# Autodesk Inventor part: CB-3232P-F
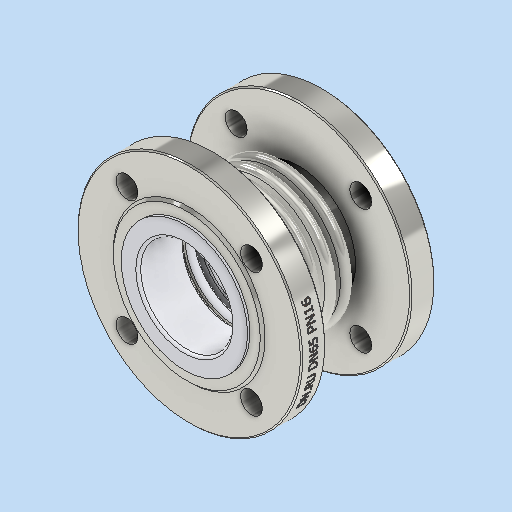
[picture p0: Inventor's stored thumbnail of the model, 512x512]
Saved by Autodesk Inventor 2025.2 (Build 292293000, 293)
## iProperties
Company: DN.RU
Created: 2026-04
Part Number: CB-3232P-F
Material: Типовые
Document SubType Name: Modeling
Designer: DN.RU
Density: 6.22746 g/cm^3
Appearance: По умолчанию
Description: D140-02139
Mass: 6300 g
Surface Area: 2420.54 cm^2
Volume: 1011.65 cm^3
Author: DN.RU
Title: Компенсатор сильфонный осевой DN.ru Ду65 Ру16
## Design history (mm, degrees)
sketch "Эскиз1"
  geometry: L1 (0, 0)-(0, -55); L2 (44, -55)-(44, 0); L3 (44, 0)-(0, 0); L4 (44, 0)-(44, -6.5); L5 (34, -6.5)-(54, -6.5); L6 (34, -10.5)-(54, -10.5); L7 (54, -2.5)-(34, -2.5); L8 (54, -8.5)-(34, -8.5); L9 (34, -4.5)-(54, -4.5); L10 (54, -15.5)-(34, -15.5); L11 (34, -17.5)-(54, -17.5); L12 (34, -19.5)-(54, -19.5); L13 (34, -23.5)-(54, -23.5); L14 (54, -21.5)-(34, -21.5); L15 (0, -55)-(44, -55); L16 (44, -55)-(38, -55); L17 (38, -55)-(38, -21.5); L18 (44, -17.5)-(42, -17.5); L19 (42, -17.5)-(42, -8.5); L20 (44, -4.5)-(42, -4.5); L21 (42, -4.5)-(42, 0); L22 (0, -55)-(0, -35); L23 (0, -35)-(92.5, -35); L24 (92.5, -35)-(92.5, -55); L25 (92.5, -55)-(0, -55); L26 (44, -35)-(44, -45); L27 (44, -45)-(47, -45); L28 (47, -45)-(47, -35); L29 (47, -35)-(44, -35); A1 r 4 centre (34, -6.5) between (34, -2.5) and (34, -10.5); A2 r 4 centre (54, -6.5) between (54, -10.5) and (54, -2.5); A3 r 2 centre (34, -6.5) between (34, -4.5) and (34, -8.5); A4 r 2 centre (54, -6.5) between (54, -8.5) and (54, -4.5); A5 r 2 centre (34, -19.5) between (34, -17.5) and (34, -21.5); A6 r 4 centre (34, -19.5) between (34, -15.5) and (34, -23.5); A7 r 2 centre (54, -19.5) between (54, -21.5) and (54, -17.5); A8 r 4 centre (54, -19.5) between (54, -23.5) and (54, -15.5); 19 further points
  constraints: 62 end point, 16 point on circle, 14 point on line, 8 centre point, 7 parallel, 4 perpendicular, 4 tangent, 3 midpoint, 2 vertical, 1 horizontal, 25 other
  dimensions: "d0" = 55 distance of L1.start L1.end; "d3" = 6.5 distance of L2.end L4.end; "d4" = 10 distance of L4.end L5.end; "d5" = 8 diameter of A2; "d6" = 2 distance between parallel lines of L6 L8; "d9" = 13 distance of L4.end point (44, -19.5); "d18" = 2 distance of L18.start L18.end; "d19" = 2 distance of L20.start L20.end; "d27" = 38 distance between parallel lines of L1 L17; "d28" = 6 distance between parallel lines of L2 L17; "d29" = 20 distance of L1.end L22.end; "d30" = 92.5 distance of L22.end L23.end; "d31" = 10 distance of L26.start L26.end; "d32" = 3 distance of L27.end L26.end
revolve "Вращение1" sketch "Эскиз1" stored, may be unused: angle "d20" = 360 deg
sketch "Эскиз3" dims "d33" = 145
  geometry: L1 (0, 0)-(54.414, 54.414); L2 (0, 0)-(76.954, 0); C1 r 9 at (51.265, 51.265); C2 r 9 at (-51.265, 51.265); C3 r 9 at (-51.265, -51.265); C4 r 9 at (51.265, -51.265); C5 r 38 at (0, 0) reference; C6 r 62.5 at (0, 0); C7 r 92.5 at (0, 0) reference; 1 further point
  constraints: 5 centre point, 4 end point, 2 coincident, 1 equal length, 1 horizontal, 1 point on line, 12 other
  dimensions: "d34" = 45 deg angle of L2 L1; "d35" = 18 diameter of C1; "d38" = 360 deg dimension on point (0, 0) C1.centre (derived); "d40" = 125 diameter of C6
  node "Эскиз — круговой массив1" dims "d38" = 360 deg (derived)
extrude "Выдавливание1" cut sketch "Эскиз3" stored distance "d41" = 10; taper "d42" = 0 deg
extrude "Выдавливание2" join sketch "Эскиз3" distance "d43" = 2; taper "d44" = 0 deg
chamfer "Фаска2" distance "d45" = 2; stored, may be unused: second distance "d46" = 2, angle "d47" = 45 deg
chamfer "Фаска3" distance "d48" = 1; stored, may be unused: second distance "d49" = 2, angle "d50" = 45 deg
mirror "Зеркальное отражение2"
fillet "Сопряжение2" dims "d51" = 1
node "РабПлоскость2"
sketch "Эскиз4"
  geometry: L1 (-44.383, 3.589)-(46.395, 3.589); L2 (46.395, 3.589)-(46.395, 0.413); L3 (46.395, 0.413)-(-44.383, 0.413); L4 (-44.383, 0.413)-(-44.383, 3.589); 1 further point
  constraints: 2 other
feature "Рельеф2" sketch "Эскиз4" dims "d3" = 6.5, "d52" = 0.1, "d53" = 0
sketch "Эскиз5"
  geometry: C1 r 38 at (0, 0) reference; C2 r 60.5 at (0, 0) reference; C3 r 52 at (0, 0); 1 further point
  constraints: 1 centre point
  dimensions: "d54" = 14 radial gap between concentric circles of C1 C3
extrude "Выдавливание3" join sketch "Эскиз5" distance "d55" = 2; taper "d56" = 0 deg
fillet "Сопряжение3" dims "d57" = 2
mirror "Зеркальное отражение3"
node "Твердое тело1"
node "Эскиз — прямоугольный массив1" dims "d9" = 13, "d12" = 10
node "Спроецированная петля1"
